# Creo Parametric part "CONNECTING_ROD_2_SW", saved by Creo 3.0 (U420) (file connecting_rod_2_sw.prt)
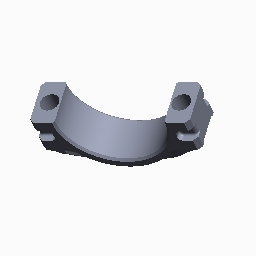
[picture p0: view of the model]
Units: millimeter Kilogram Sec (mmKs); MM, KILOGRAM, SECS

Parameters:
  CAD_SYSTEM = "SOLIDWORKS_PART"
  DEX_MASTER = "connecting_rod_2_sw(109,1547457)"
  MODEL_VERSION = "150"
  MODEL_DATE = "12/06/2013 10:03:25"
  TIM_STATUS = "Missing Ref Model"
  REF_LINK = "D:\009_demo_dev\001_Creo_Trail\engine_shaft_asm_v5\connecting_rod_2_sw.SLDPRT"
  NATIVE_NAME = "connecting_rod_2_sw(109,1547457)"

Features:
  1. coordinate system "CONNECTING_ROD_2_SW"
  2. imported feature "Import Feature id 4"
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
Layers: SHELL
